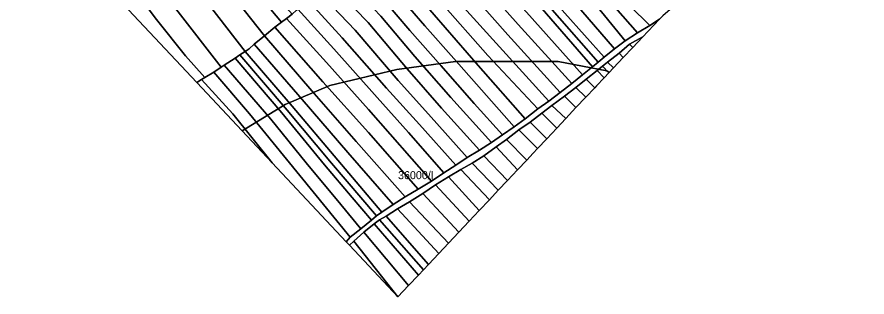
# Model space of a CAD drawing. Extents: x -537068 to -534056, y -1176840 to -1172401.
# Drawn here: x -536630 to -536099, y -1176528 to -1176353 of the extents above; entities that cross this region are included whole.
import ezdxf

# ---------------------------------------------------------------- set-up
doc = ezdxf.new("R2010")
doc.units = 0
doc.layers.add('95560013', color=7, linetype='Continuous')
doc.layers.add('95660013', color=7, linetype='Continuous')

msp = doc.modelspace()

# ---------------------------------------------------------------- linework, layer by layer
at = {"layer": '95560013'}
for points in [[(-536461.86, -1176354.15), (-536465.01, -1176356.55), (-536488.26, -1176328.66), (-536543.73, -1176258.44), (-536589.11, -1176201.99), (-536586.29, -1176195.28), (-536537.38, -1176257.24), (-536482.27, -1176324.66), (-536458.41, -1176351.52)], [(-536465.01, -1176356.55), (-536469.18, -1176359.74), (-536475.55, -1176364.96), (-536496.15, -1176338.79), (-536549.71, -1176269.42), (-536593.95, -1176212.94), (-536593.57, -1176212.62), (-536589.11, -1176201.99), (-536543.73, -1176258.44), (-536488.26, -1176328.66)], [(-536487.77, -1176374.77), (-536510.54, -1176345.38), (-536560.95, -1176279.19), (-536605.98, -1176223.35), (-536605.66, -1176222.87), (-536593.95, -1176212.94), (-536549.71, -1176269.42), (-536496.15, -1176338.79), (-536475.55, -1176364.96), (-536482.02, -1176370.25), (-536485.31, -1176373.14)], [(-536494.05, -1176378.93), (-536500.73, -1176383.35), (-536502.64, -1176384.61), (-536531.07, -1176348.2), (-536569.19, -1176297.28), (-536615.21, -1176237.17), (-536605.98, -1176223.35), (-536560.95, -1176279.19), (-536510.54, -1176345.38), (-536487.77, -1176374.77), (-536490.94, -1176376.87)], [(-536226.88, -1176352.57), (-536228.89, -1176354.7), (-536235, -1176358.52), (-536247.43, -1176346.29), (-536186.06, -1176296.38), (-536140.97, -1176257.49), (-536110.36, -1176232.59), (-536109.39, -1176233.55), (-536103.35, -1176239.06), (-536099.25, -1176242.81), (-536110.32, -1176252.33), (-536110.34, -1176252.34)], [(-536525.04, -1176377.47), (-536543.02, -1176354.95), (-536579.22, -1176306.96), (-536622.41, -1176247.94), (-536615.21, -1176237.17), (-536569.19, -1176297.28), (-536531.07, -1176348.2), (-536502.64, -1176384.61), (-536507.24, -1176387.66), (-536512.8, -1176391.01)], [(-536280.6, -1176308.27), (-536275.06, -1176314.62), (-536269.95, -1176320.48), (-536264.44, -1176326.8), (-536258.83, -1176333.24), (-536253.2, -1176339.69), (-536247.43, -1176346.29), (-536235, -1176358.52), (-536242.64, -1176363.15), (-536286.82, -1176312.85), (-536314.2, -1176282.62), (-536347.52, -1176247.26), (-536344.38, -1176242.83), (-536342.85, -1176240.67), (-536329.59, -1176255), (-536323.6, -1176261.48), (-536312.62, -1176273.35), (-536304.74, -1176281.87), (-536297.88, -1176289.27), (-536291.81, -1176295.83), (-536285.51, -1176302.64), (-536282.69, -1176305.87)], [(-536517.92, -1176394.22), (-536596.72, -1176310.19), (-536600.59, -1176306.07), (-536613.37, -1176285), (-536630.24, -1176259.65), (-536622.41, -1176247.94), (-536579.22, -1176306.96), (-536543.02, -1176354.95), (-536525.04, -1176377.47), (-536512.8, -1176391.01), (-536514.96, -1176392.31)], [(-536242.64, -1176363.15), (-536250.33, -1176368.1), (-536265.1, -1176350.1), (-536292.59, -1176317.75), (-536319.13, -1176288.03), (-536352.25, -1176253.95), (-536349.89, -1176250.61), (-536347.52, -1176247.26), (-536314.2, -1176282.62), (-536286.82, -1176312.85)], [(-536250.33, -1176368.1), (-536257.07, -1176373.1), (-536293.86, -1176330.36), (-536325.24, -1176295.49), (-536357.81, -1176261.11), (-536354.96, -1176257.77), (-536352.25, -1176253.95), (-536319.13, -1176288.03), (-536292.59, -1176317.75), (-536265.1, -1176350.1)], [(-536362.72, -1176266.53), (-536361.36, -1176265.27), (-536357.81, -1176261.11), (-536325.24, -1176295.49), (-536293.86, -1176330.36), (-536257.07, -1176373.1), (-536263.54, -1176378.48), (-536300.2, -1176336.92), (-536328.76, -1176304.42)], [(-536306.41, -1176343.51), (-536335.84, -1176310.12), (-536369.2, -1176272.54), (-536367.56, -1176271.02), (-536365.82, -1176269.4), (-536332.43, -1176307.38), (-536303.34, -1176340.16), (-536267.24, -1176381.53), (-536270.65, -1176384.45)], [(-536267.24, -1176381.53), (-536303.34, -1176340.16), (-536332.43, -1176307.38), (-536365.82, -1176269.4), (-536362.72, -1176266.53), (-536328.76, -1176304.42), (-536300.2, -1176336.92), (-536263.54, -1176378.48)], [(-536276.99, -1176389.46), (-536311.9, -1176350.18), (-536335.76, -1176324.28), (-536376.12, -1176278.95), (-536375.26, -1176278.15), (-536369.2, -1176272.54), (-536335.84, -1176310.12), (-536306.41, -1176343.51), (-536270.65, -1176384.45)], [(-536344.69, -1176326.96), (-536382.58, -1176284.93), (-536376.12, -1176278.95), (-536335.76, -1176324.28), (-536311.9, -1176350.18), (-536276.99, -1176389.46), (-536283.59, -1176394.74), (-536317.24, -1176357.94)], [(-536317.24, -1176357.94), (-536283.59, -1176394.74), (-536290.93, -1176400.43), (-536323.6, -1176364.47), (-536353.03, -1176331.1), (-536389.51, -1176291.13), (-536384.76, -1176286.95), (-536382.58, -1176284.93), (-536344.69, -1176326.96)], [(-536389.51, -1176291.13), (-536353.03, -1176331.1), (-536323.6, -1176364.47), (-536290.93, -1176400.43), (-536298.02, -1176405.77), (-536330.91, -1176369.72), (-536359.23, -1176338.11), (-536395.77, -1176296.64), (-536394.98, -1176295.94)], [(-536298.02, -1176405.77), (-536304.88, -1176410.72), (-536336.17, -1176377.28), (-536365.96, -1176343.63), (-536402.69, -1176302.72), (-536395.77, -1176296.64), (-536359.23, -1176338.11), (-536330.91, -1176369.72)], [(-536402.69, -1176302.72), (-536365.96, -1176343.63), (-536336.17, -1176377.28), (-536304.88, -1176410.72), (-536312.84, -1176416.87), (-536342.17, -1176383.5), (-536376.52, -1176344.13), (-536409.37, -1176308.36), (-536404.34, -1176304.17)], [(-536376.52, -1176344.13), (-536342.17, -1176383.5), (-536312.84, -1176416.87), (-536319.71, -1176421.86), (-536357.34, -1176379.25), (-536375.49, -1176358.73), (-536394.28, -1176337.02), (-536415.9, -1176313.81), (-536414.77, -1176312.87), (-536409.37, -1176308.36)], [(-536326.94, -1176426.79), (-536344.55, -1176407.27), (-536365.4, -1176383.51), (-536384.76, -1176361.7), (-536402, -1176341.56), (-536422.94, -1176319.68), (-536415.9, -1176313.81), (-536394.28, -1176337.02), (-536375.49, -1176358.73), (-536357.34, -1176379.25), (-536319.71, -1176421.86)], [(-536326.94, -1176426.79), (-536333.82, -1176431.63), (-536359.29, -1176403.67), (-536381.8, -1176378.04), (-536403.03, -1176352.8), (-536429.17, -1176325.16), (-536424.95, -1176321.36), (-536422.94, -1176319.68), (-536402, -1176341.56), (-536384.76, -1176361.7), (-536365.4, -1176383.51), (-536344.55, -1176407.27)], [(-536410.92, -1176356.66), (-536435.74, -1176331.08), (-536435.42, -1176330.79), (-536429.17, -1176325.16), (-536403.03, -1176352.8), (-536381.8, -1176378.04), (-536359.29, -1176403.67), (-536333.82, -1176431.63), (-536341.41, -1176436.48), (-536365.01, -1176410.23), (-536386.57, -1176385.62)], [(-536392.12, -1176393), (-536419.06, -1176361.42), (-536442.34, -1176337.03), (-536435.74, -1176331.08), (-536410.92, -1176356.66), (-536386.57, -1176385.62), (-536365.01, -1176410.23), (-536341.41, -1176436.48), (-536349.02, -1176441.01), (-536373.16, -1176414.04)], [(-536392.12, -1176393), (-536373.16, -1176414.04), (-536349.02, -1176441.01), (-536356.07, -1176445.88), (-536378.87, -1176420.5), (-536399.4, -1176397.78), (-536427.15, -1176366.41), (-536448.5, -1176342.58), (-536445.3, -1176339.69), (-536442.34, -1176337.03), (-536419.06, -1176361.42)], [(-536363.61, -1176450.71), (-536385.59, -1176425.51), (-536405.22, -1176403.63), (-536432.38, -1176373.27), (-536454.89, -1176348.34), (-536448.5, -1176342.58), (-536427.15, -1176366.41), (-536399.4, -1176397.78), (-536378.87, -1176420.5), (-536356.07, -1176445.88)], [(-536436.89, -1176381.79), (-536461.86, -1176354.15), (-536458.41, -1176351.52), (-536455.64, -1176349.02), (-536454.89, -1176348.34), (-536432.38, -1176373.27), (-536405.22, -1176403.63), (-536385.59, -1176425.51), (-536363.61, -1176450.71), (-536371.28, -1176455.77), (-536383.62, -1176441.86), (-536410.6, -1176411.08)], [(-536410.76, -1176425.39), (-536439.12, -1176393.89), (-536469.18, -1176359.74), (-536465.01, -1176356.55), (-536461.86, -1176354.15), (-536436.89, -1176381.79), (-536410.6, -1176411.08), (-536383.62, -1176441.86), (-536371.28, -1176455.77), (-536379.55, -1176460.84)], [(-536298.02, -1176405.77), (-536290.93, -1176400.43), (-536283.59, -1176394.74), (-536276.99, -1176389.46), (-536270.65, -1176384.45), (-536267.24, -1176381.53), (-536263.54, -1176378.48), (-536257.07, -1176373.1), (-536250.33, -1176368.1), (-536242.64, -1176363.15), (-536235, -1176358.52), (-536228.89, -1176354.7), (-536239.56, -1176365.98), (-536239.72, -1176365.82), (-536247.63, -1176370.33), (-536254.07, -1176375.9), (-536261.3, -1176381.47), (-536264.5, -1176384.04), (-536267.9, -1176386.65), (-536274.78, -1176392.15), (-536281.14, -1176397.27), (-536288.27, -1176402.67), (-536296.05, -1176408.57), (-536302.46, -1176413.41), (-536309.7, -1176419.02), (-536316.75, -1176423.86), (-536324.52, -1176429.74), (-536330.98, -1176434.34), (-536338.65, -1176439.91), (-536345.91, -1176444.61), (-536352.92, -1176448.6), (-536360.76, -1176453.19), (-536368.72, -1176458.12), (-536376.82, -1176463.49), (-536384.98, -1176468.73), (-536392.59, -1176473.17), (-536399.72, -1176477.63), (-536403.8, -1176480.03), (-536407.11, -1176482.46), (-536413.48, -1176487.6), (-536419.89, -1176493.22), (-536422.6, -1176495.87), (-536424.66, -1176493.67), (-536422.07, -1176490.79), (-536415.54, -1176485.61), (-536408.86, -1176480.11), (-536405.59, -1176477.39), (-536402.38, -1176475.1), (-536395.27, -1176470.3), (-536387.73, -1176465.57), (-536379.55, -1176460.84), (-536371.28, -1176455.77), (-536363.61, -1176450.71), (-536356.07, -1176445.88), (-536349.02, -1176441.01), (-536341.41, -1176436.48), (-536333.82, -1176431.63), (-536326.94, -1176426.79), (-536319.71, -1176421.86), (-536312.84, -1176416.87), (-536304.88, -1176410.72)], [(-536410.76, -1176425.39), (-536379.55, -1176460.84), (-536387.73, -1176465.57), (-536418.34, -1176431.03), (-536446.13, -1176399.35), (-536475.55, -1176364.96), (-536469.18, -1176359.74), (-536439.12, -1176393.89)], [(-536423.58, -1176437.87), (-536452.08, -1176404.9), (-536482.02, -1176370.25), (-536475.55, -1176364.96), (-536446.13, -1176399.35), (-536418.34, -1176431.03), (-536387.73, -1176465.57), (-536395.27, -1176470.3)], [(-536239.72, -1176365.82), (-536239.56, -1176365.98), (-536245.55, -1176372.32), (-536247.63, -1176370.33)], [(-536487.77, -1176374.77), (-536485.31, -1176373.14), (-536482.02, -1176370.25), (-536452.08, -1176404.9), (-536423.58, -1176437.87), (-536395.27, -1176470.3), (-536402.38, -1176475.1), (-536429.74, -1176442.67), (-536458.33, -1176409.05)], [(-536245.55, -1176372.32), (-536251.47, -1176378.58), (-536254.07, -1176375.9), (-536247.63, -1176370.33)], [(-536433.69, -1176444.53), (-536461.53, -1176411.48), (-536490.94, -1176376.87), (-536487.77, -1176374.77), (-536458.33, -1176409.05), (-536429.74, -1176442.67), (-536402.38, -1176475.1), (-536405.59, -1176477.39)], [(-536251.47, -1176378.58), (-536257.51, -1176384.96), (-536261.3, -1176381.47), (-536254.07, -1176375.9)], [(-536420.8, -1176465.97), (-536408.86, -1176480.11), (-536415.54, -1176485.61), (-536427.96, -1176470.33), (-536449.58, -1176444.38), (-536471.74, -1176417.11), (-536500.73, -1176383.35), (-536494.05, -1176378.93), (-536464.89, -1176413.11), (-536438.19, -1176445.53)], [(-536494.05, -1176378.93), (-536490.94, -1176376.87), (-536461.53, -1176411.48), (-536433.69, -1176444.53), (-536405.59, -1176477.39), (-536408.86, -1176480.11), (-536420.8, -1176465.97), (-536438.19, -1176445.53), (-536464.89, -1176413.11)], [(-536261.3, -1176381.47), (-536257.51, -1176384.96), (-536260.46, -1176388.08), (-536264.5, -1176384.04)], [(-536507.24, -1176387.66), (-536502.64, -1176384.61), (-536500.73, -1176383.35), (-536471.74, -1176417.11), (-536449.58, -1176444.38), (-536427.96, -1176470.33), (-536415.54, -1176485.61), (-536422.07, -1176490.79), (-536484.92, -1176413.82)], [(-536267.9, -1176386.65), (-536263.44, -1176391.23), (-536268.3, -1176396.37), (-536269.36, -1176397.5), (-536274.78, -1176392.15)], [(-536263.44, -1176391.23), (-536267.9, -1176386.65), (-536264.5, -1176384.04), (-536260.46, -1176388.08)], [(-536495.36, -1176413.72), (-536470.9, -1176444.37), (-536517.92, -1176394.22), (-536514.96, -1176392.31)], [(-536507.24, -1176387.66), (-536484.92, -1176413.82), (-536422.07, -1176490.79), (-536424.66, -1176493.67), (-536470.9, -1176444.37), (-536495.36, -1176413.72), (-536514.96, -1176392.31), (-536512.8, -1176391.01)], [(-536269.36, -1176397.5), (-536274.94, -1176403.42), (-536281.14, -1176397.27), (-536274.78, -1176392.15)], [(-536274.94, -1176403.42), (-536281.04, -1176409.9), (-536288.27, -1176402.67), (-536281.14, -1176397.27)], [(-536287.42, -1176416.69), (-536296.05, -1176408.57), (-536288.27, -1176402.67), (-536281.04, -1176409.9)], [(-536309.7, -1176419.02), (-536302.46, -1176413.41), (-536293.06, -1176422.68), (-536299.32, -1176429.33)], [(-536302.46, -1176413.41), (-536296.05, -1176408.57), (-536287.42, -1176416.69), (-536293.06, -1176422.68)], [(-536324.52, -1176429.74), (-536316.75, -1176423.86), (-536305.12, -1176435.49), (-536307.84, -1176438.38), (-536311.84, -1176442.63)], [(-536309.7, -1176419.02), (-536299.32, -1176429.33), (-536305.12, -1176435.49), (-536316.75, -1176423.86)], [(-536323.89, -1176455.43), (-536338.65, -1176439.91), (-536330.98, -1176434.34), (-536317.64, -1176448.79)], [(-536330.98, -1176434.34), (-536324.52, -1176429.74), (-536311.84, -1176442.63), (-536317.64, -1176448.79)], [(-536338.65, -1176439.91), (-536323.89, -1176455.43), (-536329.6, -1176461.5), (-536345.91, -1176444.61)], [(-536352.92, -1176448.6), (-536345.91, -1176444.61), (-536329.6, -1176461.5), (-536335.16, -1176467.41)], [(-536352.92, -1176448.6), (-536335.16, -1176467.41), (-536341.45, -1176474.08), (-536360.76, -1176453.19)], [(-536368.72, -1176458.12), (-536360.76, -1176453.19), (-536341.45, -1176474.08), (-536347.82, -1176480.86)], [(-536368.72, -1176458.12), (-536347.82, -1176480.86), (-536354.21, -1176487.65), (-536376.82, -1176463.49)], [(-536376.82, -1176463.49), (-536354.21, -1176487.65), (-536360.7, -1176494.54), (-536384.98, -1176468.73)], [(-536392.59, -1176473.17), (-536384.98, -1176468.73), (-536360.7, -1176494.54), (-536366.78, -1176501)], [(-536399.72, -1176477.63), (-536392.59, -1176473.17), (-536366.78, -1176501), (-536373.27, -1176507.9)], [(-536385.63, -1176521.03), (-536413.48, -1176487.6), (-536407.11, -1176482.46), (-536379.5, -1176514.52)], [(-536376.32, -1176511.14), (-536379.5, -1176514.52), (-536407.11, -1176482.46), (-536403.8, -1176480.03)], [(-536403.8, -1176480.03), (-536399.72, -1176477.63), (-536373.27, -1176507.9), (-536376.32, -1176511.14)], [(-536392.33, -1176528.15), (-536419.89, -1176493.22), (-536413.48, -1176487.6), (-536385.63, -1176521.03)], [(-536419.89, -1176493.22), (-536392.33, -1176528.15), (-536422.6, -1176495.87)]]:
    msp.add_lwpolyline(points, close=True, dxfattribs=at)
at = {"layer": '95660013'}
msp.add_lwpolyline([(-536226.88, -1176352.57), (-536228.89, -1176354.7), (-536239.56, -1176365.98), (-536245.55, -1176372.32), (-536251.47, -1176378.58), (-536257.51, -1176384.96), (-536260.26, -1176387.87), (-536261.81, -1176387), (-536292.12, -1176381), (-536356.37, -1176381), (-536393, -1176386), (-536434.87, -1176396), (-536462.62, -1176408), (-536489.56, -1176424.47), (-536517.92, -1176394.22), (-536596.72, -1176310.19)], dxfattribs=at)
msp.add_lwpolyline([(-536379.5, -1176514.52), (-536385.63, -1176521.03), (-536392.33, -1176528.15), (-536422.6, -1176495.87), (-536424.66, -1176493.67), (-536470.9, -1176444.37), (-536489.56, -1176424.47), (-536462.62, -1176408), (-536434.87, -1176396), (-536393, -1176386), (-536356.37, -1176381), (-536292.12, -1176381), (-536261.81, -1176387), (-536260.26, -1176387.87), (-536260.46, -1176388.08), (-536263.44, -1176391.23), (-536268.3, -1176396.37), (-536269.36, -1176397.5), (-536274.94, -1176403.42), (-536281.04, -1176409.9), (-536287.42, -1176416.69), (-536293.06, -1176422.68), (-536299.32, -1176429.33), (-536305.12, -1176435.49), (-536307.84, -1176438.38), (-536311.84, -1176442.63), (-536317.64, -1176448.79), (-536323.89, -1176455.43), (-536329.6, -1176461.5), (-536335.16, -1176467.41), (-536341.45, -1176474.08), (-536347.82, -1176480.86), (-536354.21, -1176487.65), (-536360.7, -1176494.54), (-536366.78, -1176501), (-536373.27, -1176507.9), (-536376.32, -1176511.14)], close=True, dxfattribs=at)

# ---------------------------------------------------------------- texts
msp.add_text('36000/I.', height=5, rotation=360, dxfattribs=at).set_placement((-536392.21, -1176454.57))

doc.saveas('drawing.dxf')
